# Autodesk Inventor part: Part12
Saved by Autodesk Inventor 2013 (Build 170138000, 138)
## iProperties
Created: 2012-07
Part Number: Part12
Material: Generic
Document SubType Name: Modeling
Designer: Paul
Density: 1 g/cm^3
Author: Paul
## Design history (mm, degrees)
node "User Library-Arduino Mega.SAT1"
body "Solid1"
node "Base1"
